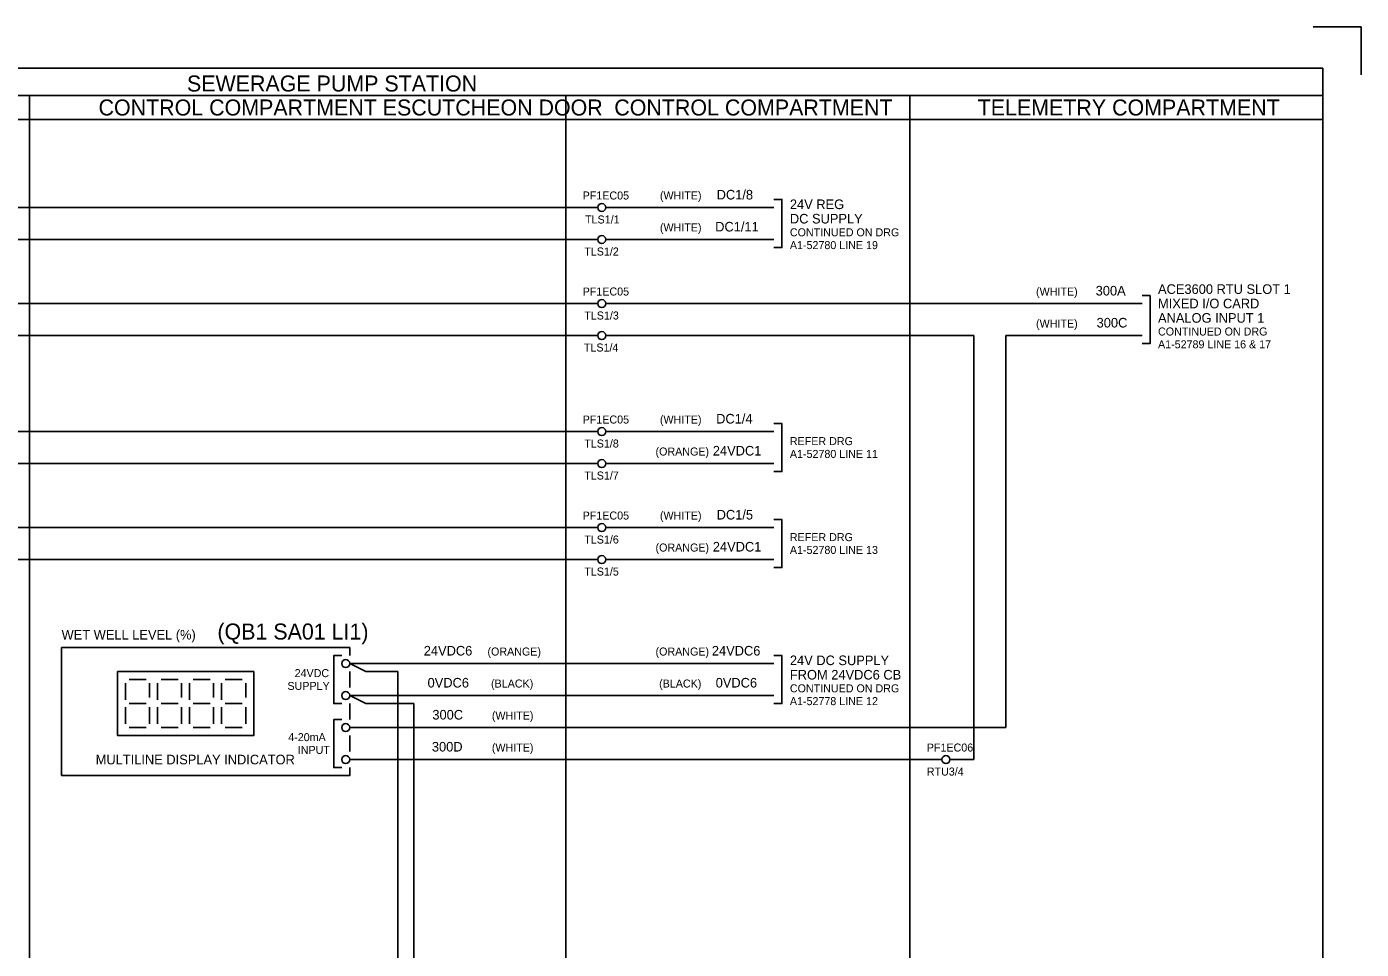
# Model space of a CAD drawing. Extents: x 0 to 841, y 0 to 594.
# Drawn here: x 424.1 to 841, y 305.7 to 594 of the extents above; entities that cross this region are included whole.
import ezdxf

# ---------------------------------------------------------------- set-up
doc = ezdxf.new("R2010")
doc.units = 0
for name, color, linetype in [('A1BORDER', 7, 'Continuous'), ('BASE', 7, 'Continuous'), ('Level 1', 7, 'Continuous'), ('Level 10', 7, 'Continuous'), ('Level 2', 7, 'Continuous')]:
    doc.layers.add(name, color=color, linetype=linetype)

msp = doc.modelspace()

# ---------------------------------------------------------------- linework, layer by layer
at = {"layer": 'A1BORDER'}
for p, q in [((826, 594), (841, 594)), ((841, 579), (841, 594)), ((28, 581), (829, 581)), ((829, 581), (829, 15))]:
    msp.add_line(p, q, dxfattribs=at)
at = {"layer": 'BASE'}
for p, q in [((317.5, 537.5), (602.5, 537.5)), ((317.5, 527.5), (602.5, 527.5)), ((317.5, 507.5), (602.5, 507.5)), ((317.5, 497.5), (602.5, 497.5))]:
    msp.add_line(p, q, dxfattribs=at)
at = {"layer": 'Level 1'}
for p, q in [((120, 572.5), (829, 572.5)), ((425, 57.5), (425, 572.5)), ((592.5, 69), (592.5, 572.5)), ((700, 69), (700, 572.5)), ((120, 565), (829, 565)), ((602.5, 537.5), (602.5, 537.5)), ((657.5, 537.5), (605, 537.5)), ((605, 537.5), (605, 537.5)), ((602.5, 527.5), (602.5, 527.5)), ((657.5, 527.5), (605, 527.5)), ((605, 527.5), (605, 527.5)), ((602.5, 507.5), (602.5, 507.5)), ((772.5, 507.5), (605, 507.5)), ((605, 507.5), (605, 507.5)), ((602.5, 497.5), (602.5, 497.5)), ((720, 497.5), (605, 497.5)), ((605, 497.5), (605, 497.5)), ((720, 497.5), (720, 365)), ((772.5, 497.5), (730, 497.5)), ((730, 497.5), (730, 375)), ((602.5, 467.5), (317.5, 467.5)), ((602.5, 467.5), (602.5, 467.5)), ((657.5, 467.5), (605, 467.5)), ((605, 467.5), (605, 467.5)), ((602.5, 457.5), (317.5, 457.5)), ((602.5, 457.5), (602.5, 457.5)), ((657.5, 457.5), (605, 457.5)), ((605, 457.5), (605, 457.5)), ((602.5, 437.5), (317.5, 437.5)), ((602.5, 437.5), (602.5, 437.5)), ((605, 437.5), (605, 437.5)), ((657.5, 437.5), (605, 437.5)), ((602.5, 427.5), (317.5, 427.5)), ((602.5, 427.5), (602.5, 427.5)), ((605, 427.5), (605, 427.5)), ((657.5, 427.5), (605, 427.5)), ((657.5, 395), (525, 395)), ((525, 395), (530, 392.5)), ((530, 392.5), (540, 392.5)), ((540, 392.5), (540, 270)), ((525, 385), (657.5, 385)), ((525, 385), (530, 382.5)), ((530, 382.5), (545, 382.5)), ((545, 382.5), (545, 260)), ((525, 375), (730, 375)), ((710, 365), (525, 365)), ((710, 365), (710, 365)), ((720, 365), (712.5, 365)), ((712.5, 365), (712.5, 365))]:
    msp.add_line(p, q, dxfattribs=at)
for points in [[(657.5, 525), (660, 525), (660, 540), (657.5, 540)], [(772.5, 495), (775, 495), (775, 510), (772.5, 510)], [(657.5, 455), (660, 455), (660, 470), (657.5, 470)], [(657.5, 425), (660, 425), (660, 440), (657.5, 440)], [(522.5, 397.5), (520, 397.5), (520, 382.5), (522.5, 382.5)], [(657.5, 382.5), (660, 382.5), (660, 397.5), (657.5, 397.5)], [(522.5, 377.5), (520, 377.5), (520, 362.5), (522.5, 362.5)]]:
    msp.add_lwpolyline(points, dxfattribs=at)
msp.add_lwpolyline([(452.5, 392.5), (495, 392.5), (495, 372.5), (452.5, 372.5)], close=True, dxfattribs=at)
at = {"layer": 'Level 10'}
for centre in [(603.75, 537.5), (603.75, 527.5), (603.75, 507.5), (603.75, 497.5), (603.75, 467.5), (603.75, 457.5), (603.75, 437.5), (603.75, 427.5), (523.75, 395), (523.75, 385), (523.75, 375), (523.75, 365), (711.25, 365)]:
    msp.add_circle(centre, 1.25, dxfattribs=at)
at = {"layer": 'Level 2'}
for p, q in [((455, 388.88), (455, 383.63)), ((456.13, 390), (461.37, 390)), ((462.5, 388.88), (462.5, 384.38)), ((465, 388.88), (465, 383.63)), ((466.13, 390), (471.37, 390)), ((472.5, 388.88), (472.5, 384.38)), ((475, 388.88), (475, 383.63)), ((476.13, 390), (481.37, 390)), ((482.5, 388.88), (482.5, 384.38)), ((485, 388.88), (485, 383.63)), ((486.13, 390), (491.37, 390)), ((492.5, 388.88), (492.5, 384.38)), ((455, 381.38), (455, 376.13)), ((456.13, 382.5), (461.37, 382.5)), ((462.5, 381.38), (462.5, 376.13)), ((465, 381.38), (465, 376.13)), ((466.13, 382.5), (471.37, 382.5)), ((472.5, 381.38), (472.5, 376.13)), ((475, 381.38), (475, 376.13)), ((476.13, 382.5), (481.37, 382.5)), ((482.5, 381.38), (482.5, 376.13)), ((485, 381.38), (485, 376.13)), ((486.13, 382.5), (491.37, 382.5)), ((492.5, 381.38), (492.5, 376.13)), ((456.13, 375), (461.37, 375)), ((466.13, 375), (471.37, 375)), ((476.13, 375), (481.37, 375)), ((486.13, 375), (491.37, 375))]:
    msp.add_line(p, q, dxfattribs=at)
for points in [[(525, 397.5), (525, 400), (435, 400), (435, 360)], [(525, 387.5), (525, 392.5)], [(525, 377.5), (525, 382.5)], [(525, 367.5), (525, 372.5)], [(435, 360), (525, 360), (525, 362.5)]]:
    msp.add_lwpolyline(points, dxfattribs=at)

# ---------------------------------------------------------------- texts
at = {"layer": 'Level 1'}
for s, height, p in [('SEWERAGE PUMP STATION', 5, (474.16, 573.75)), ('CONTROL COMPARTMENT ESCUTCHEON DOOR', 5, (446.54, 566.25)), ('CONTROL COMPARTMENT', 5, (607.65, 566.25)), ('TELEMETRY COMPARTMENT', 5, (721.16, 566.25)), ('PF1EC05', 2.5, (597.77, 540)), ('(WHITE)', 2.5, (621.9, 540)), ('DC1/8', 3, (639.62, 540)), ('24V REG', 3, (662.5, 537)), ('TLS1/1', 2.5, (598.52, 532.5)), ('DC SUPPLY', 3, (662.5, 532.5)), ('(WHITE)', 2.5, (621.9, 530)), ('DC1/11', 3, (639.17, 530)), ('CONTINUED ON DRG', 2.5, (662.5, 528.5)), ('A1-52780 LINE 19', 2.5, (662.5, 524.5)), ('TLS1/2', 2.5, (598.27, 522.5)), ('300A', 3, (758.02, 510)), ('ACE3600 RTU SLOT 1', 3, (777.5, 510.5)), ('PF1EC05', 2.5, (597.77, 510)), ('(WHITE)', 2.5, (739.4, 510)), ('MIXED I/O CARD', 3, (777.5, 506)), ('TLS1/3', 2.5, (598.27, 502.5)), ('ANALOG INPUT 1', 3, (777.5, 501.5)), ('(WHITE)', 2.5, (739.4, 500)), ('300C', 3, (758.32, 500)), ('CONTINUED ON DRG', 2.5, (777.5, 497.5)), ('TLS1/4', 2.5, (598.15, 492.5)), ('A1-52789 LINE 16 & 17', 2.5, (777.5, 493.5)), ('PF1EC05', 2.5, (597.77, 470)), ('(WHITE)', 2.5, (621.9, 470)), ('DC1/4', 3, (639.47, 470)), ('TLS1/8', 2.5, (598.27, 462.5)), ('24VDC1', 3, (638.43, 460)), ('REFER DRG', 2.5, (662.5, 463.25)), ('(ORANGE)', 2.5, (620.53, 460)), ('A1-52780 LINE 11', 2.5, (662.5, 459.25)), ('TLS1/7', 2.5, (598.27, 452.5)), ('PF1EC05', 2.5, (597.77, 440)), ('(WHITE)', 2.5, (621.9, 440)), ('DC1/5', 3, (639.62, 440)), ('TLS1/6', 2.5, (598.27, 432.5)), ('REFER DRG', 2.5, (662.5, 433.25)), ('(ORANGE)', 2.5, (620.53, 430)), ('24VDC1', 3, (638.43, 430)), ('A1-52780 LINE 13', 2.5, (662.5, 429.25)), ('TLS1/5', 2.5, (598.27, 422.5)), ('WET WELL LEVEL (%)', 3, (435, 402.5)), ('(QB1 SA01 LI1)', 5, (483.67, 402.5)), ('24VDC6', 3, (548.13, 397.5)), ('24VDC6', 3, (638.13, 397.5)), ('(ORANGE)', 2.5, (568.03, 397.5)), ('(ORANGE)', 2.5, (620.53, 397.5)), ('24V DC SUPPLY', 3, (662.5, 394.5)), ('24VDC', 2.5, (507.79, 390.75)), ('FROM 24VDC6 CB', 3, (662.5, 390)), ('SUPPLY', 2.5, (505.55, 386.75)), ('0VDC6', 3, (549.32, 387.5)), ('(BLACK)', 2.5, (569.15, 387.5)), ('(BLACK)', 2.5, (621.65, 387.5)), ('0VDC6', 3, (639.32, 387.5)), ('CONTINUED ON DRG', 2.5, (662.5, 386)), ('A1-52778 LINE 12', 2.5, (662.5, 382)), ('300C', 3, (550.82, 377.5)), ('(WHITE)', 2.5, (569.4, 377.5)), ('4-20mA', 2.5, (505.8, 370.75)), ('INPUT', 2.5, (508.78, 366.75)), ('300D', 3, (550.67, 367.5)), ('(WHITE)', 2.5, (569.4, 367.5)), ('PF1EC06', 2.5, (705.27, 367.5)), ('RTU3/4', 2.5, (705.27, 360))]:
    msp.add_text(s, height=height, dxfattribs=at).set_placement(p)
at = {"layer": 'Level 2'}
msp.add_text('MULTILINE DISPLAY INDICATOR', height=3, dxfattribs=at).set_placement((445.66, 363.5))

doc.saveas('drawing.dxf')
